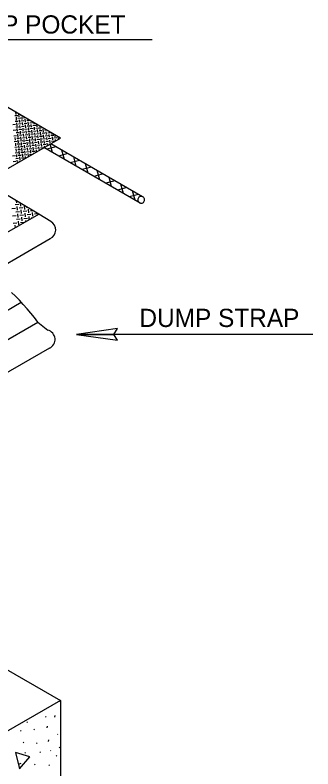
# Model space of a CAD drawing. Extents: x -120.7 to -50.3, y -20.2 to 3.8.
# Drawn here: x -73.811 to -71.852, y -6.372 to -1.409 of the extents above; entities that cross this region are included whole.
import ezdxf

# ---------------------------------------------------------------- set-up
doc = ezdxf.new("R2010")
doc.units = 0
for name, color, linetype in [('Default', 7, 'Continuous'), ('HATCH', 7, 'Continuous'), ('PR_Dimensions', 7, 'Continuous'), ('PR_Pattern_Area', 7, 'Continuous'), ('TYP_Typical_Section_Linework', 7, 'Continuous'), ('TYP_Typical_Section_Txt', 7, 'Continuous')]:
    doc.layers.add(name, color=color, linetype=linetype)

# ---------------------------------------------------------------- blocks, each defined once
blk = doc.blocks.new('ISOSACK_1')
at = {"layer": 'HATCH'}
for p, q in [((1501928.27, 358139.43), (1501927.08, 358139.32)), ((1501927.62, 358139.97), (1501927.54, 358140.87)), ((1501928.91, 358138.89), (1501928.81, 358140.08)), ((1501929.81, 358139.56), (1501929.45, 358139.53)), ((1501928.47, 358137.06), (1501927.29, 358136.95)), ((1501927.82, 358137.59), (1501927.72, 358138.77)), ((1501928.03, 358135.21), (1501927.92, 358136.4)), ((1501929.56, 358138.34), (1501928.37, 358138.24)), ((1501929.76, 358135.97), (1501928.58, 358135.87)), ((1501929.12, 358136.52), (1501929.02, 358137.7)), ((1501930.85, 358137.26), (1501929.66, 358137.16)), ((1501930.19, 358137.79), (1501930.09, 358138.98)), ((1501930.4, 358135.42), (1501930.3, 358136.61)), ((1501931.61, 358138.52), (1501930.74, 358138.45)), ((1501932.14, 358136.18), (1501930.95, 358136.07)), ((1501931.49, 358136.72), (1501931.39, 358137.91)), ((1501933.22, 358137.47), (1501932.03, 358137.37)), ((1501932.77, 358135.63), (1501932.67, 358136.82)), ((1501934.51, 358136.39), (1501933.32, 358136.28)), ((1501933.86, 358136.93), (1501933.84, 358137.24)), ((1501935.14, 358135.84), (1501935.09, 358136.52)), ((1501927.38, 358135.76), (1501926.2, 358135.65)), ((1501927.59, 358133.38), (1501926.4, 358133.28)), ((1501928.67, 358134.67), (1501927.49, 358134.57)), ((1501928.23, 358132.83), (1501928.12, 358134.02)), ((1501929.96, 358133.59), (1501928.78, 358133.49)), ((1501929.33, 358134.14), (1501929.22, 358135.33)), ((1501929.52, 358131.75), (1501929.41, 358132.94)), ((1501931.05, 358134.89), (1501929.87, 358134.79)), ((1501930.61, 358133.05), (1501930.5, 358134.24)), ((1501932.34, 358133.81), (1501931.16, 358133.7)), ((1501931.7, 358134.35), (1501931.6, 358135.54)), ((1501931.91, 358131.98), (1501931.8, 358133.16)), ((1501933.43, 358135.1), (1501932.24, 358134.99)), ((1501933.63, 358132.73), (1501932.45, 358132.62)), ((1501932.98, 358133.26), (1501932.88, 358134.44)), ((1501934.72, 358134.01), (1501933.53, 358133.91)), ((1501934.07, 358134.56), (1501933.97, 358135.74)), ((1501934.28, 358132.18), (1501934.18, 358133.37)), ((1501935.8, 358135.31), (1501934.61, 358135.2)), ((1501936.01, 358132.93), (1501934.82, 358132.83)), ((1501935.35, 358133.46), (1501935.25, 358134.65)), ((1501937.09, 358134.22), (1501935.9, 358134.12)), ((1501936.43, 358134.75), (1501936.34, 358135.79)), ((1501936.65, 358132.39), (1501936.55, 358133.58)), ((1501937, 358135.41), (1501936.98, 358135.41)), ((1501938.38, 358133.14), (1501937.19, 358133.03)), ((1501937.73, 358133.68), (1501937.63, 358134.86)), ((1501938.8, 358134.37), (1501938.28, 358134.33)), ((1501939.02, 358132.59), (1501938.91, 358133.77)), ((1501940.6, 358133.33), (1501939.56, 358133.24)), ((1501940.31, 358131.52), (1501940.21, 358132.71)), ((1501941.39, 358132.8), (1501941.38, 358132.88)), ((1501927.8, 358131.01), (1501926.61, 358130.91)), ((1501927.35, 358129.17), (1501927.25, 358130.36)), ((1501928.88, 358132.3), (1501927.69, 358132.19)), ((1501929.09, 358129.93), (1501927.9, 358129.82)), ((1501928.43, 358130.46), (1501928.33, 358131.64)), ((1501930.17, 358131.22), (1501928.98, 358131.11)), ((1501929.72, 358129.38), (1501929.62, 358130.56)), ((1501931.25, 358132.51), (1501930.07, 358132.4)), ((1501931.46, 358130.13), (1501930.27, 358130.03)), ((1501930.81, 358130.67), (1501930.71, 358131.86)), ((1501932.54, 358131.43), (1501931.36, 358131.32)), ((1501932.1, 358129.58), (1501931.99, 358130.77)), ((1501933.83, 358130.34), (1501932.65, 358130.24)), ((1501933.2, 358130.89), (1501933.09, 358132.08)), ((1501933.39, 358128.51), (1501933.29, 358129.69)), ((1501934.92, 358131.64), (1501933.74, 358131.54)), ((1501934.49, 358129.81), (1501934.38, 358131)), ((1501936.21, 358130.56), (1501935.03, 358130.45)), ((1501935.57, 358131.1), (1501935.46, 358132.29)), ((1501935.78, 358128.73), (1501935.67, 358129.92)), ((1501937.3, 358131.85), (1501936.11, 358131.75)), ((1501936.85, 358130.01), (1501936.75, 358131.2)), ((1501938.59, 358130.77), (1501937.4, 358130.66)), ((1501937.94, 358131.31), (1501937.84, 358132.5)), ((1501938.15, 358128.94), (1501938.05, 358130.13)), ((1501939.67, 358132.06), (1501938.48, 358131.95)), ((1501939.88, 358129.69), (1501938.69, 358129.58)), ((1501939.22, 358130.22), (1501939.12, 358131.4)), ((1501940.96, 358130.97), (1501939.77, 358130.87)), ((1501940.52, 358129.15), (1501940.42, 358130.33)), ((1501942.04, 358132.27), (1501940.86, 358132.16)), ((1501942.25, 358129.89), (1501941.06, 358129.79)), ((1501941.6, 358130.42), (1501941.49, 358131.61)), ((1501943.33, 358131.18), (1501942.14, 358131.08)), ((1501942.69, 358131.73), (1501942.65, 358132.15)), ((1501942.89, 358129.35), (1501942.79, 358130.54)), ((1501944.62, 358130.1), (1501943.43, 358130)), ((1501943.97, 358130.63), (1501943.9, 358131.43)), ((1501945.26, 358129.55), (1501945.16, 358130.7)), ((1501945.99, 358130.22), (1501945.81, 358130.2)), ((1501928.01, 358128.64), (1501926.82, 358128.54)), ((1501927.56, 358126.8), (1501927.46, 358127.98)), ((1501929.3, 358127.55), (1501928.11, 358127.45)), ((1501928.64, 358128.09), (1501928.54, 358129.27)), ((1501928.85, 358125.71), (1501928.75, 358126.9)), ((1501930.38, 358128.85), (1501929.19, 358128.74)), ((1501930.59, 358126.47), (1501929.4, 358126.37)), ((1501929.93, 358127), (1501929.83, 358128.19)), ((1501931.67, 358127.76), (1501930.48, 358127.66)), ((1501931.02, 358128.3), (1501930.92, 358129.49)), ((1501931.23, 358125.93), (1501931.12, 358127.11)), ((1501932.75, 358129.05), (1501931.56, 358128.95)), ((1501932.96, 358126.68), (1501931.77, 358126.57)), ((1501932.31, 358127.22), (1501932.21, 358128.4)), ((1501934.04, 358127.97), (1501932.85, 358127.87)), ((1501933.6, 358126.13), (1501933.49, 358127.31)), ((1501935.12, 358129.26), (1501933.94, 358129.15)), ((1501935.33, 358126.89), (1501934.14, 358126.78)), ((1501934.69, 358127.43), (1501934.58, 358128.62)), ((1501936.41, 358128.18), (1501935.23, 358128.07)), ((1501935.97, 358126.34), (1501935.86, 358127.52)), ((1501937.5, 358129.48), (1501936.32, 358129.37)), ((1501937.7, 358127.09), (1501936.52, 358126.99)), ((1501937.06, 358127.64), (1501936.96, 358128.82)), ((1501937.26, 358125.25), (1501937.15, 358126.44)), ((1501938.79, 358128.39), (1501937.61, 358128.29)), ((1501938.36, 358126.57), (1501938.25, 358127.75)), ((1501940.08, 358127.31), (1501938.9, 358127.21)), ((1501939.43, 358127.84), (1501939.33, 358129.03)), ((1501939.57, 358126.25), (1501939.54, 358126.66)), ((1501941.17, 358128.6), (1501939.98, 358128.5)), ((1501940.72, 358126.91), (1501940.62, 358127.96)), ((1501941.66, 358127.45), (1501941.27, 358127.42)), ((1501941.8, 358128.05), (1501941.7, 358129.24)), ((1501943.54, 358128.81), (1501942.35, 358128.7)), ((1501944.12, 358128.87), (1501944.07, 358129.45)), ((1501928.21, 358126.27), (1501927.03, 358126.16)), ((1501928.42, 358123.89), (1501927.23, 358123.79)), ((1501927.77, 358124.42), (1501927.66, 358125.61)), ((1501927.98, 358122.06), (1501927.88, 358123.25)), ((1501929.5, 358125.18), (1501928.32, 358125.08)), ((1501929.06, 358123.35), (1501928.96, 358124.54)), ((1501930.79, 358124.1), (1501929.61, 358123.99)), ((1501930.15, 358124.64), (1501930.04, 358125.82)), ((1501930.36, 358122.27), (1501930.25, 358123.46)), ((1501931.88, 358125.39), (1501930.69, 358125.29)), ((1501931.43, 358123.55), (1501931.33, 358124.74)), ((1501933.17, 358124.31), (1501931.98, 358124.2)), ((1501932.52, 358124.85), (1501932.42, 358126.04)), ((1501932.73, 358122.48), (1501932.62, 358123.67)), ((1501934.25, 358125.6), (1501933.06, 358125.49)), ((1501933.8, 358123.76), (1501933.7, 358124.94)), ((1501935.54, 358124.51), (1501934.35, 358124.41)), ((1501934.89, 358125.06), (1501934.79, 358126.25)), ((1501935.02, 358123.62), (1501935, 358123.87)), ((1501936.62, 358125.81), (1501935.43, 358125.7)), ((1501936.15, 358124.27), (1501936.07, 358125.15)), ((1501936.75, 358124.62), (1501936.72, 358124.62)), ((1501938.99, 358126.01), (1501937.81, 358125.91)), ((1501927.34, 358122.6), (1501926.15, 358122.5)), ((1501927.54, 358120.22), (1501926.35, 358120.11)), ((1501928.63, 358121.52), (1501927.44, 358121.41)), ((1501928.19, 358119.69), (1501928.09, 358120.88)), ((1501929.71, 358122.81), (1501928.53, 358122.71)), ((1501929.44, 358120.4), (1501928.73, 358120.33)), ((1501929.27, 358120.97), (1501929.16, 358122.16)), ((1501931, 358121.73), (1501929.81, 358121.62)), ((1501930.47, 358120.99), (1501930.46, 358121.09)), ((1501932.08, 358123.02), (1501930.9, 358122.91)), ((1501931.6, 358121.64), (1501931.53, 358122.36)), ((1501934.32, 358123.21), (1501933.27, 358123.12)), ((1501928.76, 358102.24), (1501927.24, 358102.11)), ((1501927.92, 358102.92), (1501927.85, 358103.74)), ((1501928.19, 358099.89), (1501928.05, 358101.41)), ((1501929.57, 358101.54), (1501929.46, 358102.78)), ((1501931.23, 358100.16), (1501931.1, 358101.68)), ((1501927.37, 358100.59), (1501925.85, 358100.46)), ((1501929.02, 358099.21), (1501927.5, 358099.07)), ((1501928.46, 358096.86), (1501928.33, 358098.38)), ((1501930.41, 358100.86), (1501928.89, 358100.72)), ((1501929.85, 358098.51), (1501929.71, 358100.03)), ((1501932.06, 358099.47), (1501930.54, 358099.34)), ((1501931.5, 358097.13), (1501931.37, 358098.65)), ((1501932.4, 358101.03), (1501931.93, 358100.99)), ((1501933.71, 358098.09), (1501932.19, 358097.95)), ((1501932.87, 358098.76), (1501932.74, 358100.28)), ((1501934.64, 358099.7), (1501933.58, 358099.6)), ((1501934.54, 358097.4), (1501934.4, 358098.92)), ((1501936.75, 358098.35), (1501935.23, 358098.22)), ((1501927.64, 358097.55), (1501926.12, 358097.42)), ((1501929.29, 358096.17), (1501927.77, 358096.03)), ((1501928.73, 358093.83), (1501928.6, 358095.35)), ((1501930.68, 358097.82), (1501929.16, 358097.69)), ((1501930.1, 358095.46), (1501929.97, 358096.98)), ((1501932.33, 358096.43), (1501930.81, 358096.3)), ((1501931.68, 358095.05), (1501931.63, 358095.61)), ((1501933.13, 358095.9), (1501933.01, 358097.25)), ((1501934.32, 358096.61), (1501933.84, 358096.57)), ((1501927.89, 358094.5), (1501926.37, 358094.37)), ((1501927.31, 358092.47), (1501927.2, 358093.69)), ((1501928.22, 358093), (1501928.03, 358092.99)), ((1501930.94, 358094.78), (1501929.42, 358094.65))]:
    blk.add_line(p, q, dxfattribs=at)
blk = doc.blocks.new('AR32_1')
at = {"layer": 'Default'}
for p, q in [((0, 0), (-11.43, 1.6)), ((-11.43, 1.6), (-10.39, -0.01)), ((-11.42, -1.63), (0, 0)), ((-10.39, -0.01), (-11.42, -1.63))]:
    blk.add_line(p, q, dxfattribs=at)

msp = doc.modelspace()

# ---------------------------------------------------------------- linework, layer by layer
at = {"layer": 'PR_Dimensions'}
for p, q in [((-72.9097, -1.571), (-74.5842, -1.571)), ((-73.1383, -3.4731), (-73.4081, -3.5115)), ((-73.1627, -3.5112), (-73.1383, -3.4731)), ((-71.8525, -3.5115), (-73.4081, -3.5115)), ((-73.4081, -3.5115), (-73.1627, -3.5115)), ((-73.4081, -3.5115), (-73.1382, -3.5492)), ((-73.1382, -3.5492), (-73.1624, -3.5115))]:
    msp.add_line(p, q, dxfattribs=at)
for points in [[(-73.1624, -3.5115), (-73.1627, -3.5115), (-73.4081, -3.5115)], [(-73.1627, -3.5115), (-73.1627, -3.5112)]]:
    msp.add_lwpolyline(points, dxfattribs=at)
at = {"layer": 'PR_Pattern_Area'}
for p, q in [((-73.5157, -5.9336), (-73.512, -5.9299)), ((-73.5924, -5.9684), (-73.5921, -5.9687)), ((-73.6119, -6.0277), (-73.6075, -6.0321)), ((-73.5507, -6.0211), (-73.5528, -6.0321)), ((-73.7345, -6.0671), (-73.7301, -6.0627)), ((-73.601, -6.0911), (-73.6031, -6.1021)), ((-73.7761, -6.1197), (-73.7717, -6.1241)), ((-73.6886, -6.1153), (-73.6842, -6.1109)), ((-73.5309, -6.1437), (-73.5331, -6.1459)), ((-73.7587, -6.2007), (-73.7543, -6.1963)), ((-73.6711, -6.205), (-73.6667, -6.2006)), ((-73.5923, -6.1809), (-73.5944, -6.1919)), ((-73.5769, -6.251), (-73.5791, -6.2532)), ((-73.5222, -6.2335), (-73.5178, -6.2291)), ((-73.7476, -6.2685), (-73.7433, -6.2641)), ((-73.6492, -6.2641), (-73.6448, -6.2597)), ((-73.5419, -6.2882), (-73.5375, -6.2838)), ((-73.7827, -6.3385), (-73.7717, -6.3342)), ((-73.6842, -6.3451), (-73.6798, -6.3407)), ((-73.59, -6.3451), (-73.5856, -6.3495))]:
    msp.add_line(p, q, dxfattribs=at)
msp.add_lwpolyline([(-73.7818, -6.3712), (-73.7144, -6.2935), (-73.8075, -6.265), (-73.7829, -6.3712)], dxfattribs=at)
at = {"layer": 'TYP_Typical_Section_Linework'}
for p, q in [((-73.5114, -2.2182), (-73.9586, -1.96)), ((-75.8114, -3.5462), (-73.5114, -2.2182)), ((-72.9891, -2.6466), (-73.6212, -2.2817)), ((-73.5416, -2.276), (-73.6027, -2.2923)), ((-73.564, -2.3147), (-73.5793, -2.2575)), ((-72.9721, -2.6048), (-73.5765, -2.2558)), ((-73.4641, -2.3207), (-73.5253, -2.3371)), ((-73.4865, -2.3595), (-73.5029, -2.2983)), ((-73.3866, -2.3654), (-73.4478, -2.3818)), ((-73.409, -2.4042), (-73.4254, -2.3431)), ((-73.3092, -2.4102), (-73.3703, -2.4266)), ((-73.3315, -2.4489), (-73.3479, -2.3878)), ((-73.2317, -2.4549), (-73.2928, -2.4713)), ((-73.254, -2.4937), (-73.2704, -2.4325)), ((-73.1766, -2.5384), (-73.1929, -2.4773)), ((-73.6555, -2.7192), (-74.0114, -2.5069)), ((-73.1542, -2.4997), (-73.2153, -2.516)), ((-73.0991, -2.5831), (-73.1154, -2.522)), ((-73.0767, -2.5444), (-73.1378, -2.5608)), ((-73.0216, -2.6279), (-73.038, -2.5668)), ((-72.9992, -2.5891), (-73.0603, -2.6055)), ((-74.1141, -2.984), (-73.6555, -2.7192)), ((-73.5758, -2.7686), (-73.6555, -2.7192)), ((-73.9855, -3.1143), (-73.5804, -2.8805)), ((-74.0491, -3.4608), (-73.7701, -3.2997)), ((-73.9601, -3.6028), (-73.6615, -3.4304)), ((-73.6615, -3.4304), (-73.5968, -3.4837)), ((-73.5853, -3.6017), (-73.9008, -3.7849)), ((-75.937, -4.5219), (-73.512, -5.922)), ((-73.512, -5.922), (-75.3126, -6.9615)), ((-73.512, -5.922), (-73.512, -8.27))]:
    msp.add_line(p, q, dxfattribs=at)
msp.add_lwpolyline([(-72.9744, -2.647), (-72.9707, -2.6454), (-72.9671, -2.6429), (-72.9639, -2.6394), (-72.9614, -2.635), (-72.9599, -2.63), (-72.9596, -2.6248), (-72.9604, -2.6197), (-72.9621, -2.6151), (-72.9645, -2.6112), (-72.9673, -2.6082), (-72.9706, -2.6057), (-72.9746, -2.6037), (-72.9792, -2.6025), (-72.9841, -2.6023), (-72.9891, -2.6033), (-72.9937, -2.6055), (-72.9975, -2.6086), (-73.0004, -2.6124), (-73.0024, -2.6164), (-73.0035, -2.6204), (-73.0039, -2.6245), (-73.0035, -2.629), (-73.0021, -2.6337), (-72.9996, -2.6383), (-72.9961, -2.6422), (-72.9919, -2.6453), (-72.9873, -2.6472), (-72.9826, -2.6481), (-72.9783, -2.648)], close=True, dxfattribs=at)
msp.add_lwpolyline([(-73.6615, -3.4304), (-73.6844, -3.4002), (-73.7079, -3.3707), (-73.7321, -3.342), (-73.7569, -3.3141), (-73.7824, -3.2869), (-73.8086, -3.2606), (-73.8355, -3.2349)], dxfattribs=at)
for centre, end in [((-73.6059, -2.8234), 61.3035), ((-73.6107, -3.5446), 77.1301)]:
    msp.add_arc(centre, 0.0625, 293.9985, end, dxfattribs=at)

# ---------------------------------------------------------------- block references
at = {"layer": 'PR_Dimensions', "xscale": 0.023622, "yscale": 0.023622, "rotation": -179.99999999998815}
msp.add_blockref('AR32_1', (-73.4081, -3.5115), dxfattribs=at)
at = {"layer": 'PR_Pattern_Area', "xscale": 0.015747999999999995, "yscale": 0.015747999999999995}
msp.add_blockref('ISOSACK_1', (-23726.1605, -5642.0509), dxfattribs=at)

# ---------------------------------------------------------------- texts
at = {"layer": 'TYP_Typical_Section_Txt'}
for s, p in [('FLAP POCKET', (-74.1909, -1.5306)), ('DUMP STRAP', (-72.9934, -3.4626))]:
    msp.add_text(s, height=0.12, dxfattribs=at).set_placement(p)

doc.saveas('drawing.dxf')
